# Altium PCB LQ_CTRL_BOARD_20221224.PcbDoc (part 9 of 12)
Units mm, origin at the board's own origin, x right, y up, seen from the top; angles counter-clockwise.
Board outline 260 x 142 mm, 6 copper layers (Top Layer, Mid-Layer 1, Mid-Layer 2, Mid-Layer 3, Mid-Layer 4, Bottom Layer); 1105 components, 1039 nets, 3898 pads, 1277 vias.
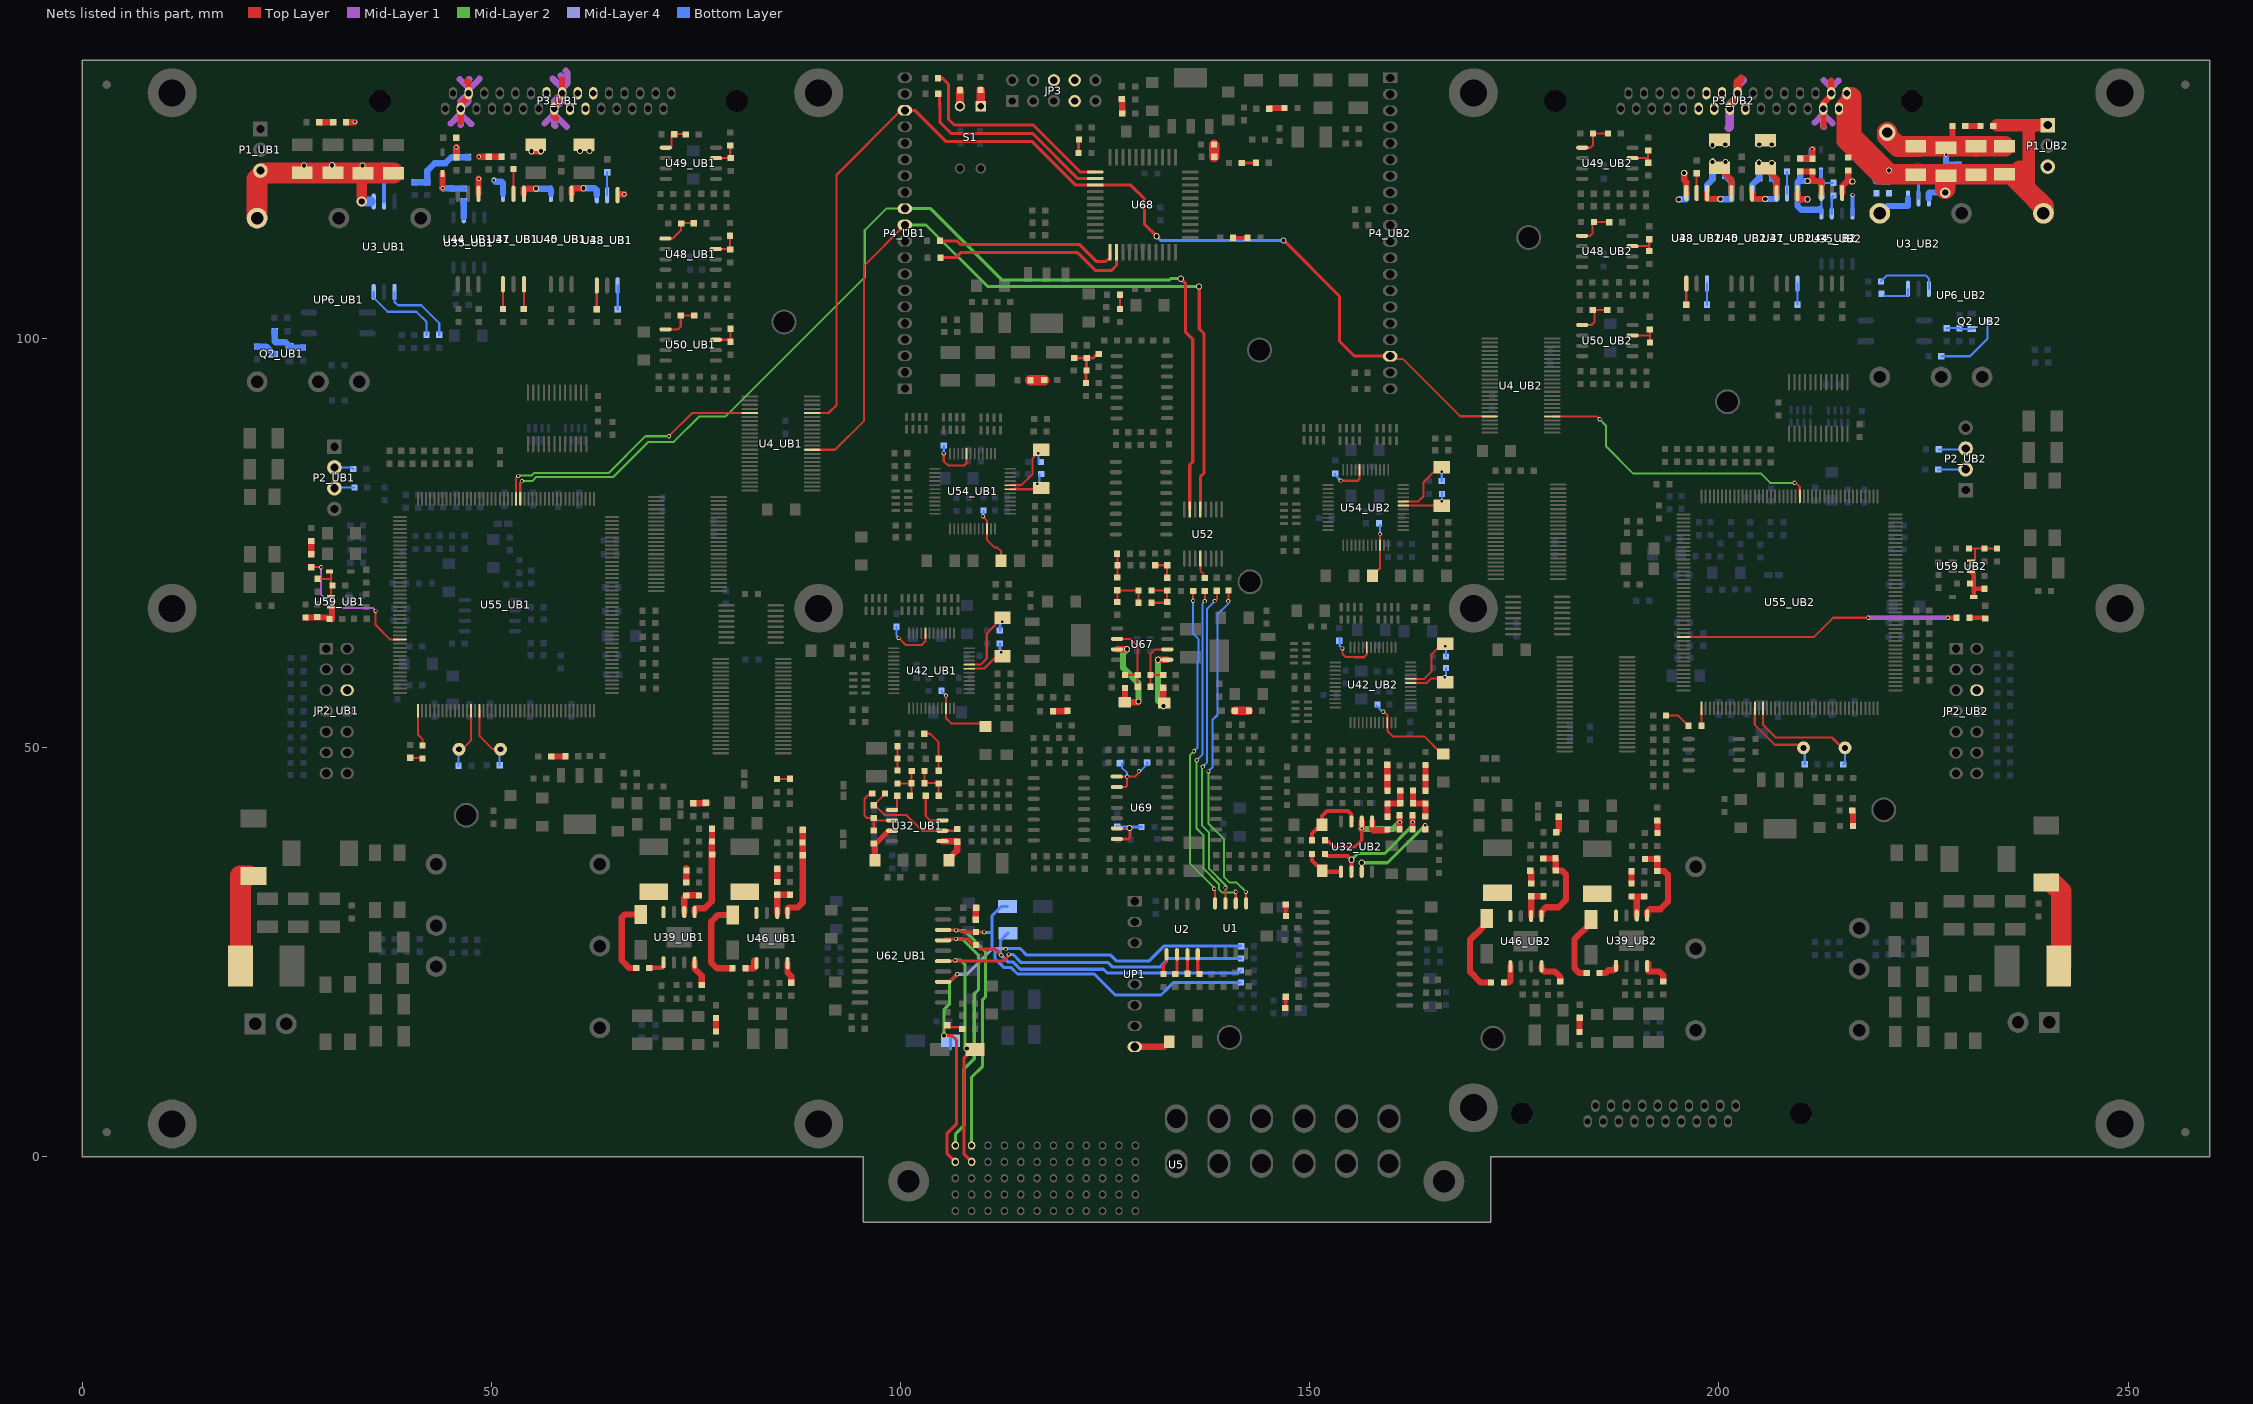
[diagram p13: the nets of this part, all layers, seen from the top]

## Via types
v1: diameter 0.508, hole 0.305, Top Layer to Bottom Layer, 845 vias
v2: diameter 0.762, hole 0.508, Top Layer to Bottom Layer, 317 vias
v3: diameter 1.27, hole 0.762, Top Layer to Bottom Layer, 77 vias
v4: diameter 2.032, hole 1.524, Top Layer to Bottom Layer, 15 vias
v5: diameter 2.032, hole 1.27, Top Layer to Bottom Layer, 11 vias
v6: diameter 1.27, hole 0.711, Top Layer to Bottom Layer, 8 vias
v7: diameter 2.54, hole 1.778, Top Layer to Bottom Layer, 3 vias
v8: diameter 1.524, hole 1.016, Top Layer to Bottom Layer, 1 vias

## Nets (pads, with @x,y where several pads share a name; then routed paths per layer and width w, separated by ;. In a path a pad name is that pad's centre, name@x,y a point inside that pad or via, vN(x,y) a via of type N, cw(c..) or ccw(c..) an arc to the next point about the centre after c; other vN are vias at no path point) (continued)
ISO_+15V_UB2: C12_UB2.1 C13_UB2.2 C14_UB2.2 C15_UB2.2 C256_UB2.1 C257_UB2.1 C278_UB2.1 C279_UB2.1 C280_UB2.2 C281_UB2.2 C282_UB2.2 C283_UB2.1 C305_UB2.2 C306_UB2.2 C307_UB2.2 C308_UB2.2 LED10_UB2.1 P1_UB2.1 P3_UB2.1 P3_UB2.16 R192_UB2.1 U3_UB2.6 U35_UB2.1 U35_UB2.4 U37_UB2.6 U38_UB2.6 U40_UB2.6 U41_UB2.6 U43_UB2.6 U44_UB2.6 U45_UB2.6 UP6_UB2.3 | length 114.9
  Top Layer w0.762: v2(195.758,120.193) 195.758,119.355 196.017,119.095 U38_UB2.6@196.017,117.754 ; C257_UB2.1@200.076,120.828 200.101,120.828 201.529,119.4 U45_UB2.6@201.529,117.729 ; C256_UB2.1@205.689,120.802 207.06,119.432 U41_UB2.6@207.06,117.729 ; C307_UB2.2@209.931,120.396 209.956,120.371 C308_UB2.2@211.43,120.371 211.43,119.253 211.455,119.228 ; v2(210.845,119.228) 211.455,119.228 ; U44_UB2.6@212.527,117.754 212.527,119.121 212.42,119.228 211.455,119.228 ; v3(227.658,117.805) v3@227.66,117.803 ; 237.298,125.959 237.851,125.405
  Top Layer w1.016: 216.281,130.124 214.859,128.702 214.859,123.952 219.558,119.253 ; 219.583,119.278 221.691,119.278
  Top Layer w1.524: 233.959,126.009 234.01,126.06 238.506,126.06 ; C279_UB2.1@235.735,120.04 236.675,120.98 237.851,120.98 ; 237.298,125.959 238.404,125.959 ; 237.679,118.096 237.851,118.268 237.851,120.98 ; P1_UB2.1@240.182,126.06 238.506,126.06 ; 237.851,120.98 237.851,125.405 238.404,125.959 ; 238.404,125.959 238.506,126.06
  Top Layer w2.54: 216.179,123.977 216.179,129.464 ; 216.281,124.638 220.878,120.04 C279_UB2.1@234.905,120.04 235.735,120.04 237.679,118.096 239.658,116.118 UP6_UB2.3@239.658,115.275 ; v3@227.66,118.313 C283_UB2.1@227.66,119.863
  Bottom Layer w0.254: U35_UB2.1@212.522,115.189 U35_UB2.1@212.522,115.24 212.522,117.399 R192_UB2.1@212.547,117.424
  Bottom Layer w0.508: U35_UB2.4@216.332,115.189 v1@216.332,117.504
  Bottom Layer w0.762: U43_UB2.6@198.557,117.754 198.557,118.75 199.238,119.431 v2(199.238,121.564) ; U40_UB2.6@204.069,117.729 204.069,118.75 204.902,119.583 v2(204.902,121.463) ; C282_UB2.2@209.931,120.396 209.931,119.378 209.781,119.228 ; v2(210.845,119.228) 209.781,119.228 ; U35_UB2.1@212.369,115.875 212.217,115.722 210.083,115.722 209.6,116.206 U37_UB2.6@209.6,117.729 209.6,119.046 209.781,119.228 ; U3_UB2.6@225.654,117.094 225.654,117.704 225.755,117.805 v3(227.658,117.805) 227.762,117.909 C14_UB2.2@227.762,119.659 C13_UB2.2@229.286,119.659
  Bottom Layer w1.016: C15_UB2.2@219.253,119.304 C306_UB2.2@220.777,119.304 v2(220.777,120.523)
  other v1: 216.337,117.526
  other v2: 206.451,121.437 200.812,121.539
ISO_GND_UB1: C12_UB1.2 C13_UB1.1 C14_UB1.1 C15_UB1.1 C256_UB1.2 C257_UB1.2 C278_UB1.2 C279_UB1.2 C280_UB1.1 C281_UB1.1 C282_UB1.1 C283_UB1.2 C305_UB1.1 C306_UB1.1 C307_UB1.1 C308_UB1.1 P1_UB1.3 P3_UB1.2 P3_UB1.8 P3_UB1.17 P3_UB1.23 R275_UB1.1 U3_UB1.4 U37_UB1.4 U38_UB1.4 U40_UB1.4 U41_UB1.4 U43_UB1.4 U44_UB1.4 U45_UB1.4 UP6_UB1.5 | length 100.5
  Top Layer w0.762: R275_UB1.1@32.258,126.416 33.299,126.416 v1(33.325,126.441) ; C281_UB1.1@45.745,122.123 v1(45.745,123.342) ; 46.177,126.416 46.279,126.517 P3_UB1.2@46.279,128.047 46.279,128.6 47.231,129.552 P3_UB1.17@47.231,129.952 47.231,131.204 47.015,131.42 ; U44_UB1.4@48.444,117.653 48.444,119.507 v1(48.463,119.507) ; v1(48.489,122.199) C14_UB1.1@49.682,122.199 C282_UB1.1@51.257,122.199 ; U37_UB1.4@53.98,117.653 53.98,118.268 v2@55.479,118.268 ; C256_UB1.2@55.428,123.647 55.428,123.373 v2(54.915,122.86) 56.044,122.86 v2(56.058,122.873) ; 57.887,126.873 57.709,127.051 P3_UB1.8@57.709,128.047 57.709,128.422 58.661,129.374 P3_UB1.23@58.661,129.952 58.661,131.61 58.674,131.623 ; U40_UB1.4@59.822,117.653 59.822,118.344 v2(61.259,118.344) v2@61.265,118.339 ; U43_UB1.4@65.634,117.602 v1(66.243,117.602)
  Top Layer w1.27: v3(34.163,116.713) 34.163,120.046 C279_UB1.2@34.31,120.193
  Top Layer w2.54: UP6_UB1.5@21.385,114.691 21.385,119.429 22.149,120.193 C279_UB1.2@34.31,120.193 C278_UB1.2@38.044,120.193
  Mid-Layer 1 w0.762: 45.034,126.238 P3_UB1.2@46.279,127.483 ; 46.152,131.648 P3_UB1.17@47.231,130.569 ; 46.228,126.06 46.279,126.111 P3_UB1.2@46.279,127.406 ; 47.295,131.699 47.231,131.635 P3_UB1.17@47.231,130.569 ; 47.549,126.187 47.523,126.213 47.473,126.213 P3_UB1.2@46.279,127.406 ; 48.565,131.724 P3_UB1.17@47.231,130.39 ; 56.515,126.263 P3_UB1.8@57.709,127.457 ; 57.48,131.75 P3_UB1.23@58.661,130.569 ; 57.785,125.933 57.81,125.959 57.709,126.06 P3_UB1.8@57.709,127.377 ; 58.496,132.105 58.661,131.941 P3_UB1.23@58.661,130.569 ; 59.106,132.69 59.309,132.486 59.309,131.14 P3_UB1.23@58.661,130.492 ; 59.233,125.853 P3_UB1.8@57.709,127.377 ; P3_UB1.2@46.279,127.406 P3_UB1.2@46.279,127.483 ; P3_UB1.2@46.279,127.483 P3_UB1.2@46.279,128.047 ; P3_UB1.2@46.279,128.047 47.231,128.999 P3_UB1.17@47.231,129.952 ; P3_UB1.2@46.279,128.047 46.279,129 P3_UB1.17@47.231,129.952 ; P3_UB1.17@47.231,129.952 P3_UB1.17@47.231,130.39 ; P3_UB1.17@47.231,130.39 P3_UB1.17@47.231,130.569 ; P3_UB1.8@57.709,127.377 P3_UB1.8@57.709,127.457 ; P3_UB1.8@57.709,127.457 P3_UB1.8@57.709,128.047 ; P3_UB1.8@57.709,128.047 58.661,128.999 P3_UB1.23@58.661,129.952 ; P3_UB1.8@57.709,128.047 57.709,129 P3_UB1.23@58.661,129.952 ; P3_UB1.23@58.661,129.952 P3_UB1.23@58.661,130.492 ; P3_UB1.23@58.661,130.492 P3_UB1.23@58.661,130.569
  Bottom Layer w0.762: C280_UB1.1@40.64,119.075 42.164,119.075 C13_UB1.1@42.189,119.05 ; C13_UB1.1@42.189,119.075 42.189,120.498 43.078,121.387 44.399,121.387 45.136,122.123 C305_UB1.1@45.745,122.123 ; v1(45.745,123.342) C305_UB1.1@45.745,122.123 ; C306_UB1.1@47.168,122.123 C305_UB1.1@45.745,122.123 ; v1(50.317,119.329) 50.521,119.126 51.257,119.126 51.44,118.943 U41_UB1.4@51.44,117.653 ; v2(55.474,118.288) 57.15,118.288 57.282,118.155 U45_UB1.4@57.282,117.653 ; v2(61.259,118.344) 62.631,118.344 62.89,118.085 U38_UB1.4@62.89,117.5
  Bottom Layer w1.27: v3(34.163,116.713) 35.204,116.713
  other v2: 27.102,121.133 34.265,121.133 30.556,121.158 62.001,122.885 60.833,122.911
ISO_GND_UB2: C12_UB2.2 C13_UB2.1 C14_UB2.1 C15_UB2.1 C256_UB2.2 C257_UB2.2 C278_UB2.2 C279_UB2.2 C280_UB2.1 C281_UB2.1 C282_UB2.1 C283_UB2.2 C305_UB2.1 C306_UB2.1 C307_UB2.1 C308_UB2.1 P1_UB2.3 P3_UB2.2 P3_UB2.8 P3_UB2.17 P3_UB2.23 R275_UB2.1 U3_UB2.4 U37_UB2.4 U38_UB2.4 U40_UB2.4 U41_UB2.4 U43_UB2.4 U44_UB2.4 U45_UB2.4 UP6_UB2.5 | length 79.1
  Top Layer w0.762: U38_UB2.4@198.557,117.754 198.557,117.063 198.603,117.018 v2(200.177,117.018) ; U45_UB2.4@204.069,117.729 204.069,117.216 204.267,117.018 v2(205.664,117.018) ; U41_UB2.4@209.6,117.729 209.6,117.07 209.677,116.992 v2(210.82,116.992) ; C307_UB2.1@209.931,121.971 211.404,121.971 C308_UB2.1@211.43,121.945 211.43,123.038 211.48,123.088 211.455,123.114 v1(211.43,123.114) ; P3_UB2.17@212.766,128.047 P3_UB2.17@212.766,128.695 ; 212.776,125.984 P3_UB2.17@212.776,128.055 ; P3_UB2.17@212.801,128.753 P3_UB2.2@213.753,129.705 ; 213.69,131.47 213.718,131.443 P3_UB2.2@213.718,129.952 ; U44_UB2.4@215.067,117.754 215.067,118.573 215.671,119.177 ; C305_UB2.1@215.798,120.523 215.798,119.304 215.671,119.177 ; v2(216.306,119.177) 215.671,119.177 ; C283_UB2.2@227.736,123.292 227.914,123.469 228.54,124.095 R275_UB2.1@228.54,125.959
  Top Layer w1.016: P3_UB2.23@201.336,128.047 201.336,128.514 202.288,129.466 P3_UB2.8@202.288,129.952 202.288,131.295 202.692,131.699
  Top Layer w2.54: v5(220.574,125.146) 220.574,124.739 221.869,123.444 C12_UB2.2@224.053,123.444 ; C12_UB2.2@224.516,123.444 C12_UB2.2@224.053,123.444 ; C278_UB2.2@231.419,123.444 C278_UB2.2@231.419,123.469 ; C279_UB2.2@234.905,123.469 C278_UB2.2@231.419,123.469 ; C12_UB2.2@224.053,123.444 224.079,123.469 227.914,123.469 C278_UB2.2@231.419,123.469
  Mid-Layer 1 w0.762: 211.709,126.365 P3_UB2.17@212.766,127.422 ; P3_UB2.17@212.766,128.047 P3_UB2.17@212.766,127.422 ; 212.827,125.832 212.766,125.892 P3_UB2.17@212.766,127.391 ; 212.827,131.521 212.827,131.54 213.718,130.648 P3_UB2.2@213.718,130.584 ; P3_UB2.2@213.718,129.952 P3_UB2.2@213.718,130.584 ; 213.893,126.263 P3_UB2.17@212.766,127.391 ; 214.605,131.47 P3_UB2.2@213.718,130.584 ; P3_UB2.17@212.766,127.391 P3_UB2.17@212.766,127.422
  Mid-Layer 1 w1.016: 201.219,125.73 201.336,125.847 P3_UB2.23@201.336,128.047 201.336,128.514 202.288,129.466 P3_UB2.8@202.288,129.952 202.288,130.882 202.946,131.54
  Bottom Layer w0.762: v2@195.275,116.992 196.017,116.992 U43_UB2.4@196.017,117.754 ; v2(200.177,117.018) 200.197,116.998 201.529,116.998 U40_UB2.4@201.529,117.729 201.529,119.121 C280_UB2.1@200.787,119.863 ; v2(205.664,117.018) 206.985,117.018 207.086,117.119 207.06,117.146 U37_UB2.4@207.06,117.729 207.06,119 C281_UB2.1@206.502,119.558 ; C282_UB2.1@209.931,121.971 211.328,121.971 211.353,121.945 211.353,123.038 v1(211.43,123.114) ; UP6_UB2.5@219.658,115.275 220.562,116.18 223.114,116.18 U3_UB2.4@223.114,117.094 ; v1(227.762,122.403) C14_UB2.1@227.762,121.234 C13_UB2.1@229.286,121.234
  Bottom Layer w1.016: P3_UB2.23@201.336,128.047 201.336,128.565 202.288,129.517 P3_UB2.8@202.288,129.952
  other v2: 195.097,116.967 199.238,123.596 200.787,123.673 204.927,123.673 206.451,123.698
LED1_UB1: R347_UB1.1 U55_UB1.89 | length 4.5
  Top Layer w0.254: U55_UB1.89@41.04,54.491 41.04,53.232 41.04,51.579 41.605,51.014 R347_UB1.1@41.605,50.241
LED1_UB2: R347_UB2.1 U55_UB2.89 | length 2.1
  Top Layer w0.254: R347_UB2.1@197.866,52.654 197.885,52.673 U55_UB2.89@197.885,54.796
LED2_UB1: R41_UB1.1 U55_UB1.75 | length 17.6
  Top Layer w0.254: R41_UB1.1@27.991,72.034 29.197,72.034 29.235,71.996 29.235,72.009 v1(29.21,72.034) ; v1(35.87,66.691) 35.87,64.968 37.647,63.191 U55_UB1.75@38.84,63.191
  Mid-Layer 1 w0.254: v1(29.21,72.034) 29.21,68.682 30.861,67.031 34.505,67.031 34.531,67.056 35.505,67.056 v1(35.87,66.691)
LED2_UB2: R41_UB2.1 U55_UB2.75 | length 34.3
  Top Layer w0.254: U55_UB2.75@195.685,63.496 211.603,63.496 213.97,65.862 v1(218.262,65.862)
  Top Layer w0.508: v1(227.99,65.862) R41_UB2.1@229.033,65.862
  Mid-Layer 1 w0.508: v1(218.262,65.862) v1(227.99,65.862)
M_EXT_IO_IN1: R391.2 U68.2 | length 25.7
  Top Layer w0.381: 104.775,128.397 R391.2@104.775,129.896 ; 104.826,128.778 104.826,126.39 106.172,125.044 116.129,125.044 121.653,119.52 U68.2@123.8,119.52
M_EXT_IO_IN2: R392.2 U68.1 | length 26.3
  Top Layer w0.381: R392.2@104.775,131.775 105.131,131.775 105.867,131.039 105.867,126.771 106.578,126.06 116.214,126.06 121.955,120.32 U68.1@123.8,120.32
M_EXT_IO_OUT1: R393.2 U68.13 | length 24.6
  Top Layer w0.381: R393.2@104.877,109.855 106.756,109.855 107.366,110.465 121.539,110.465 ; 121.59,110.414 121.539,110.465 ; U68.13@126.4,110.52 126.4,108.899 125.806,108.306 123.8,108.306 121.641,110.465 121.539,110.465
M_EXT_IO_OUT2: R394.2 U68.12 | length 22.7
  Top Layer w0.381: R394.2@104.826,111.912 106.883,111.912 107.315,111.481 121.844,111.481 123.927,109.398 125.12,109.398 125.6,109.877 U68.12@125.6,110.52
M_RS422_A: DR6.2 R366_UB1.2 R421.1 U5.E2 U62_UB1.18 | length 75.4
  Top Layer w0.381: U62_UB1.18@105.212,27.711 107.213,27.711 107.467,27.457 R366_UB1.2@109.22,27.457 v1@110.211,27.457
  Mid-Layer 2 w0.381: v1(106.807,27.661) 107.772,27.661 110.388,25.044 110.388,19.533 110.033,19.177 110.033,11.074 108.7,9.742 U5.E2@108.7,1.373
  Bottom Layer w0.254: R421.1@141.326,21.285 R421.1@141.605,21.285
  Bottom Layer w0.381: v1(110.236,27.407) 111.1,27.407 111.176,27.33 ; DR6.2@113.073,30.582 112.311,30.582 111.176,29.446 111.176,27.33 ; 132.651,20.587 132.639,20.574 ; R421.1@141.326,21.285 133.35,21.285 132.639,20.574 ; 111.176,27.33 111.176,25.451 111.557,25.07 111.557,24.181 112.598,23.139 113.487,23.139 114.3,22.327 123.673,22.327 126.238,19.761 131.826,19.761 132.639,20.574
M_RS422_B: DR8.2 R366_UB1.1 R422.1 U5.E1 U62_UB1.17 | length 70
  Top Layer w0.381: U62_UB1.17@105.212,26.441 105.39,26.619 v1(106.782,26.619) 108.153,26.619 108.89,25.883 R366_UB1.1@109.22,25.883 109.728,25.375 111.557,25.375 v1(112.319,24.613)
  Mid-Layer 2 w0.381: U5.E1@106.7,1.373 106.7,2.738 107.798,3.835 107.798,10.744 ; v1(106.782,26.619) 107.518,26.619 109.525,24.613 109.525,20.422 109.017,19.914 109.017,11.963 107.798,10.744 ; 108.267,11.214 107.798,10.744
  Bottom Layer w0.254: R422.1@141.275,22.454 R422.1@141.58,22.758
  Bottom Layer w0.381: DR8.2@113.124,27.305 112.23,26.411 112.23,24.701 v1(112.319,24.613) 113.157,23.774 113.784,23.774 114.647,22.911 124.816,22.911 125.273,22.454 R422.1@141.275,22.454
M_RS422_Y: DR5.2 R424.1 U5.D1 U62_UB1.13 | length 66.7
  Top Layer w0.381: U62_UB1.13@105.212,21.361 105.969,21.361 v1@106.921,22.314 ; v2(105.334,14.808) 106.274,14.808 106.858,14.224 106.858,4.013 105.664,2.819 105.664,0.409 U5.D1@106.7,-0.627
  Mid-Layer 2 w0.381: v2(105.334,14.808) 105.334,18.009 106.007,18.682 106.007,21.374 v1(106.934,22.301) ; U5.D1@106.667,-0.66 U5.D1@106.7,-0.627
  Mid-Layer 4 w0.381: v1(106.934,22.301) 108.128,22.301 111.277,25.451 v1@112.751,25.451
  Bottom Layer w0.381: 106.103,13.183 106.121,13.201 DR5.2@106.121,14.707 ; v1@112.878,25.451 114.63,25.451 115.443,24.638 125.705,24.638 126.441,23.901 130.353,23.901 132.182,25.73 R424.1@141.63,25.73
  other v1: 112.878,25.375
M_RS422_Z: DR7.2 R423.1 U5.D2 U62_UB1.15 | length 64.4
  Top Layer w0.381: U62_UB1.15@105.212,23.901 112.573,23.901 113.208,24.536 v1@113.208,24.714 ; U5.D2@108.7,-0.627 107.772,0.301 107.772,12.09 108.788,13.106 DR7.2@109.1,13.106
  Mid-Layer 2 w0.381: v1(106.705,24.003) 107.366,24.003 107.899,23.47 107.899,21.339 107.861,21.301 v2@107.861,13.233
  Bottom Layer w0.381: v1(113.233,24.714) 113.76,24.714 114.75,23.724 125.4,23.724 125.959,23.165 131.674,23.165 132.74,24.232 R423.1@141.605,24.232
  other v2: 108.102,13.233
M_SYN_CLK: P4_UB1.11 U4_UB1.11 U52.5 | length 100.5
  Top Layer w0.254: U4_UB1.11@89.205,86.382 91.995,86.382 95.555,89.941 95.555,108.875 P4_UB1.11@100.533,113.853
  Top Layer w0.381: v2@136.5,106.324 136.5,101.168 137.084,100.584 137.084,83.515 136.643,83.074 U52.5@136.643,79.087
  Mid-Layer 2 w0.381: P4_UB1.11@100.533,113.853 100.543,113.843 103.124,113.843 110.642,106.324 v2(136.474,106.324)
M_SYN_CLKIN: P4_UB1.12 U52.7 U55_UB1.19 | length 132.8
  Top Layer w0.254: U55_UB1.19@53.54,80.391 53.54,82.395 v1@53.721,82.575
  Top Layer w0.381: v2(134.239,107.29) 134.849,106.68 134.849,100.762 135.712,99.898 135.712,84.912 135.343,84.543 U52.7@135.343,79.087
  Mid-Layer 2 w0.254: v1(53.746,82.55) 54.991,82.55 55.499,83.058 64.922,83.058 69.215,87.351 72.314,87.351 ; 72.111,87.351 72.314,87.351 ; P4_UB1.12@100.533,115.853 98.276,115.853 95.631,113.208 95.631,107.467 78.588,90.424 75.387,90.424 72.314,87.351
  Mid-Layer 2 w0.381: P4_UB1.12@100.533,115.853 103.679,115.853 112.42,107.112 132.817,107.112 132.994,107.29 v2(134.239,107.29)
M_SYNC_CLK: R8.1 U52.12 | length 2.6
  Top Layer w0.254: U52.12@136.643,73.087 136.643,71.586 137.185,71.044 R8.1@137.185,70.714
MS_SLT: P4_UB1.18 P4_UB2.18 U4_UB1.20 U4_UB2.20 U68.3 | length 135.9
  Top Layer w0.254: U4_UB1.20@89.205,90.882 91.212,90.882 92.177,91.846 92.177,119.964 100.065,127.853 P4_UB1.18@100.533,127.853 ; P4_UB2.18@159.573,97.841 159.929,97.485 161.366,97.485 168.377,90.475 U4_UB2.20@172.771,90.475
  Top Layer w0.381: P4_UB1.18@100.533,127.853 101.763,127.853 105.588,124.028 116.103,124.028 121.412,118.72 U68.3@123.8,118.72 128.143,118.72 129.819,117.043 129.819,113.944 v2(131.293,112.471) ; v2(146.812,111.963) 153.645,105.131 153.645,99.644 155.448,97.841 P4_UB2.18@159.573,97.841
  Bottom Layer w0.381: v2(131.293,112.471) 131.826,111.938 143.383,111.938 143.408,111.963 v2(146.812,111.963)
MS_SLT_IN_UB1: U4_UB1.29 U55_UB1.20 | length 34.4
  Top Layer w0.254: U55_UB1.20@53.04,80.391 53.04,82.961 v1@53.34,83.261 ; v1(71.704,88.036) 74.549,90.882 U4_UB1.29@81.585,90.882
  Mid-Layer 2 w0.254: v1@53.34,83.261 54.966,83.261 55.245,83.541 64.338,83.541 68.834,88.036 v1(71.704,88.036)
  other v1: 53.289,83.185
MS_SLT_IN_UB2: U4_UB2.29 U55_UB2.20 | length 36.2
  Top Layer w0.254: U4_UB2.29@179.629,90.474 185.065,90.474 v1(185.42,90.119) ; v1@209.454,82.291 209.454,82.279 209.885,81.848 U55_UB2.20@209.885,80.696
  Mid-Layer 2 w0.254: v1(185.42,90.119) 186.207,89.332 186.207,86.792 189.535,83.464 205.156,83.464 206.273,82.347 v1(209.245,82.347)
NetC5_2: C5.2 UP1.8 | length 4.5
  Top Layer w0.762: UP1.8@128.626,13.437 132.232,13.437 C5.2@132.842,14.046
NetC224_UB1_2: C224_UB1.2 R207_UB1.2 U32_UB1.1 | length 4.5
  Top Layer w0.508: C224_UB1.2@105.933,36.246 C224_UB1.2@105.933,36.409 ; R207_UB1.2@106.872,38.557 R207_UB1.2@106.949,38.481
  Top Layer w0.762: U32_UB1.1@105.12,38.557 R207_UB1.2@106.872,38.557 ; C224_UB1.2@105.933,36.409 106.949,37.425 R207_UB1.2@106.949,38.481
NetC224_UB2_2: C224_UB2.2 R207_UB2.2 U32_UB2.1 | length 4.9
  Top Layer w0.508: R207_UB2.2@150.292,36.982 150.292,36.195 C224_UB2.2@151.536,34.95 151.663,34.823 U32_UB2.1@153.822,34.823
NetC225_UB1_1: C225_UB1.1 R195_UB1.1 R203_UB1.2 | length 5.7
  Top Layer w0.254: C225_UB1.1@102.895,51.689 103.099,51.689 103.619,51.689 104.663,50.645 104.663,50.125 R195_UB1.1@104.663,47.168
NetC225_UB2_1: C225_UB2.1 R195_UB2.1 R203_UB2.2 | length 3.1
  Top Layer w0.762: R195_UB2.1@164.16,44.729 R203_UB2.2@164.16,46.31 C225_UB2.1@164.16,47.879
NetC236_UB1_1: C236_UB1.1 R207_UB1.1 R209_UB1.2 U32_UB1.2 | length 13.6
  Top Layer w0.254: C236_UB1.1@98.12,44.399 98.12,44.334 R209_UB1.2@96.738,42.951 96.876,42.951 98.069,41.758 100.711,41.758 102.641,39.827 U32_UB1.2@105.12,39.827 106.72,39.827 R207_UB1.1@106.949,40.056
NetC236_UB1_2: C236_UB1.2 R209_UB1.1 R214_UB1.1 U32_UB1.6 | length 8.4
  Top Layer w0.254: C236_UB1.2@96.545,44.399 96.266,44.399 95.58,43.713 95.58,41.707 95.91,41.377 R209_UB1.1@96.738,41.377 ; R214_UB1.1@96.738,39.853 R209_UB1.1@96.738,41.377 ; U32_UB1.6@98.973,41.097 97.017,41.097 R209_UB1.1@96.738,41.377
NetC236_UB2_1: C236_UB2.1 R207_UB2.1 R209_UB2.2 U32_UB2.2 | length 16.1
  Top Layer w0.381: R207_UB2.1@151.867,36.982 R207_UB2.1@152.121,36.728 ; v2@155.092,36.271 v2(155.118,36.297)
  Top Layer w0.508: R207_UB2.1@152.121,36.728 154.635,36.728 155.092,36.271 U32_UB2.2@155.092,34.823
  Top Layer w0.762: R209_UB2.2@162.56,40.005 C236_UB2.1@162.56,41.504
  Mid-Layer 2 w0.381: v2(155.118,36.297) 155.88,37.059 159.156,37.059 162.585,40.488 v1(162.585,40.894)
NetC236_UB2_2: C236_UB2.2 R209_UB2.1 R214_UB2.1 U32_UB2.6 | length 13.9
  Top Layer w0.381: R214_UB2.1@151.867,38.659 152.146,38.659 152.959,37.846 155.524,37.846 156.362,38.684 v1@156.362,40.056
  Top Layer w0.762: v1@156.362,40.056 v1(156.362,40.107) U32_UB2.6@156.362,40.97 ; R209_UB2.1@160.985,40.005 C236_UB2.2@160.985,41.504
  Mid-Layer 2 w0.762: v1@156.362,40.056 160.198,40.056 v1@160.985,40.843
  other v1: 161.011,40.894
NetC241_UB1_1: C241_UB1.1 R212_UB1.1 R221_UB1.2 R222_UB1.1 | length 4.8
  Top Layer w0.254: R221_UB1.2@99.644,45.618 101.335,45.618 C241_UB1.1@101.361,45.644 ; R222_UB1.1@101.168,44.12 101.371,44.323 R212_UB1.1@101.371,47.117
NetC241_UB1_2: C241_UB1.2 R195_UB1.2 R196_UB1.1 R212_UB1.2 | length 4.7
  Top Layer w0.254: R212_UB1.2@102.946,47.117 102.946,45.655 C241_UB1.2@102.935,45.644 104.612,45.644 R195_UB1.2@104.663,45.593 R196_UB1.1@104.663,44.12
NetC241_UB2_1: C241_UB2.1 R212_UB2.1 R221_UB2.2 R222_UB2.1 | length 4.7
  Top Layer w0.762: R222_UB2.1@159.512,41.554 R221_UB2.2@159.512,43.155 161.03,43.155 R212_UB2.1@161.061,43.186 161.06,43.187 C241_UB2.1@161.06,44.761
NetC241_UB2_2: C241_UB2.2 R195_UB2.2 R196_UB2.1 R212_UB2.2 | length 4.7
  Top Layer w0.762: C241_UB2.2@162.635,44.761 162.635,43.187 R212_UB2.2@162.636,43.186 162.667,43.155 R195_UB2.2@164.16,43.155 164.16,41.636 R196_UB2.1@164.109,41.586
NetC248_UB1_1: C248_UB1.1 R219_UB1.1 R221_UB1.1 | length 3
  Top Layer w0.254: R221_UB1.1@99.644,47.193 R219_UB1.1@99.644,48.653 C248_UB1.1@99.644,50.165
NetC248_UB2_1: C248_UB2.1 R219_UB2.1 R221_UB2.1 | length 3.2
  Top Layer w0.762: C248_UB2.1@159.487,47.904 159.487,44.755 R221_UB2.1@159.512,44.729
NetC250_UB1_2: C250_UB1.2 R214_UB1.2 U32_UB1.7 | length 4.7
  Top Layer w0.254: U32_UB1.7@98.552,39.827 U32_UB1.7@98.973,39.827
  Top Layer w0.635: R214_UB1.2@96.876,38.151 U32_UB1.7@98.552,39.827
  Top Layer w0.762: C250_UB1.2@96.876,36.22 R214_UB1.2@96.876,38.151
NetC250_UB2_2: C250_UB2.2 R214_UB2.2 U32_UB2.7 | length 8.4
  Top Layer w0.508: R214_UB2.2@150.292,38.659 150.292,39.472 151.409,40.589 C250_UB2.2@151.511,40.589 151.511,41.631 152.121,42.24 154.661,42.24 155.092,41.808 U32_UB2.7@155.092,40.97
NetC252_UB1_1: C252_UB1.1 D20_UB1.2 L3_UB1.2 U39_UB1.8 | length 9.9
  Top Layer w0.762: C252_UB1.1@67.716,23.063 66.878,23.063 65.938,24.003 65.938,29.235 66.301,29.598 D20_UB1.2@68.25,29.598
NetC252_UB1_2: C252_UB1.2 U39_UB1.1 | length 2.4
  Top Layer w0.508: C252_UB1.2@69.19,23.089 70.841,23.089 71.044,23.292 U39_UB1.1@71.044,23.749
NetC252_UB2_1: C252_UB2.1 D20_UB2.2 L3_UB2.2 U39_UB2.8 | length 8.5
  Top Layer w0.762: C252_UB2.1@183.845,22.454 182.956,22.454 182.347,23.063 182.347,26.568 184.379,28.6 D20_UB2.2@184.379,28.989
NetC252_UB2_2: C252_UB2.2 U39_UB2.1 | length 2.5
  Top Layer w0.762: C252_UB2.2@185.42,22.454 186.157,22.454 186.487,22.784 187.122,22.784 187.427,23.089 U39_UB2.1@187.427,23.317
NetC258_UB1_2: C258_UB1.2 R238_UB1.1 R242_UB1.2 U39_UB1.5 | length 11.6
  Top Layer w0.762: U39_UB1.5@74.854,29.896 74.854,30.277 74.93,30.353 76.098,30.353 76.937,31.191 R238_UB1.1@76.937,38.43 ; R238_UB1.1@76.962,38.532 C258_UB1.2@76.962,40.081
NetC258_UB2_2: C258_UB2.2 R238_UB2.1 R242_UB2.2 U39_UB2.5 | length 11.3
  Top Layer w0.762: C258_UB2.2@190.957,36.373 192.43,36.373 R238_UB2.1@192.456,36.398 192.456,34.925 R242_UB2.2@192.481,34.9 193.345,34.9 193.777,34.468 193.777,31.166 192.862,30.251 191.541,30.251 191.237,29.947 U39_UB2.5@191.237,29.464
NetC267_UB1_1: C267_UB1.1 C268_UB1.1 U42_UB1.46 | length 8.8
  Top Layer w0.254: v1(105.562,56.337) 105.549,56.323 U42_UB1.46@105.549,54.785 105.549,53.608 106.197,52.959 110.007,52.959 C267_UB1.1@110.388,52.578
  Bottom Layer w0.254: C268_UB1.1@105.004,56.947 105.004,56.896 v1(105.562,56.337)
NetC267_UB2_1: C267_UB2.1 C268_UB2.1 U42_UB2.46 | length 11.9
  Top Layer w0.254: v1(159.004,54.381) 159.029,54.407 159.029,54.432 159.484,53.978 U42_UB2.46@159.484,53.05 159.484,52.022 160.147,51.359 164.008,51.359 166.167,49.2 C267_UB2.1@166.345,49.2
  Bottom Layer w0.254: C268_UB2.1@158.14,55.143 158.902,54.381 v1(159.004,54.381)
NetC273_UB1_2: C273_UB1.2 U39_UB1.4 | length 3.1
  Top Layer w0.762: U39_UB1.4@74.854,23.749 74.854,22.987 75.717,22.123 C273_UB1.2@75.717,20.98
NetC273_UB2_2: C273_UB2.2 U39_UB2.4 | length 3.7
  Top Layer w0.762: U39_UB2.4@191.414,23.597 191.414,22.631 192.735,22.631 193.192,22.174 C273_UB2.2@193.192,21.412
NetC274_UB1_2: C274_UB1.2 C275_UB1.2 U39_UB1.6 | length 3.7
  Top Layer w0.762: U39_UB1.6@73.584,29.896 73.584,31.674 C275_UB1.2@73.838,31.928 73.863,31.953 C274_UB1.2@75.387,31.953
NetC274_UB2_2: C274_UB2.2 C275_UB2.2 U39_UB2.6 | length 3.8
  Top Layer w0.762: C275_UB2.2@189.362,31.801 C274_UB2.2@190.886,31.801 ; U39_UB2.6@189.967,29.464 189.967,31.725
NetC275_UB1_1: C275_UB1.1 R245_UB1.2 | length 1.8
  Top Layer w0.762: C275_UB1.1@73.838,33.503 73.838,35.276 R245_UB1.2@73.843,35.281
NetC275_UB2_1: C275_UB2.1 R245_UB2.2 | length 1.5
  Top Layer w0.762: C275_UB2.1@189.332,33.376 R245_UB2.2@189.332,34.874
NetC290_UB1_1: C290_UB1.1 D22_UB1.2 L4_UB1.2 U46_UB1.8 | length 10.8
  Top Layer w0.762: C290_UB1.1@79.477,23.038 77.572,23.038 76.886,23.724 76.886,28.727 77.706,29.548 D22_UB1.2@79.502,29.548
NetC290_UB1_2: C290_UB1.2 U46_UB1.1 | length 2
  Top Layer w0.762: C290_UB1.2@81.051,23.038 82.093,23.038 82.144,23.089 82.144,23.952
NetC290_UB2_1: C290_UB2.1 D22_UB2.2 L4_UB2.2 U46_UB2.8 | length 9.9
  Top Layer w0.762: D22_UB2.2@171.628,28.506 170.274,27.153 170.205,27.153 169.596,26.543 169.596,22.581 170.891,21.285 C290_UB2.1@172.161,21.285
NetC290_UB2_2: C290_UB2.2 U46_UB2.1 | length 2.6
  Top Layer w0.762: C290_UB2.2@173.736,21.285 174.295,21.285 174.523,21.514 U46_UB2.1@174.523,23.266
NetC293_UB1_2: C293_UB1.2 R268_UB1.1 R273_UB1.2 U46_UB1.5 | length 11.6
  Top Layer w0.762: U46_UB1.5@86.208,29.794 86.208,30.328 86.335,30.455 87.452,30.455 88.062,31.064 C293_UB1.2@88.062,39.954
NetC293_UB2_2: C293_UB2.2 R268_UB2.1 R273_UB2.2 U46_UB2.5 | length 11.7
  Top Layer w0.762: U46_UB2.5@178.333,29.413 178.333,29.947 178.867,30.48 180.416,30.48 181.305,31.369 181.305,34.493 180.823,34.976 R273_UB2.2@180.066,34.976 180.066,36.444 R268_UB2.1@180.035,36.474 180.01,36.449 C293_UB2.2@178.537,36.449
NetC296_UB1_2: C296_UB1.2 U46_UB1.4 | length 2.6
  Top Layer w0.762: U46_UB1.4@86.208,23.647 86.208,22.504 86.665,22.047 C296_UB1.2@86.665,21.26
NetC296_UB2_2: C296_UB2.2 U46_UB2.4 | length 3.5
  Top Layer w0.762: U46_UB2.4@178.333,23.266 178.333,22.987 178.689,22.631 179.959,22.631 180.619,21.971 C296_UB2.2@180.619,21.412
NetC297_UB1_2: C297_UB1.2 C298_UB1.2 U46_UB1.6 | length 3.7
  Top Layer w0.762: U46_UB1.6@84.938,29.794 C298_UB1.2@84.938,32.004 C297_UB1.2@86.411,32.004
NetC297_UB2_2: C297_UB2.2 C298_UB2.2 U46_UB2.6 | length 3.9
  Top Layer w0.762: U46_UB2.6@177.063,29.413 C298_UB2.2@177.063,31.826 C297_UB2.2@178.562,31.826
NetC298_UB1_1: C298_UB1.1 R276_UB1.2 | length 1.6
  Top Layer w0.762: C298_UB1.1@84.938,33.579 R276_UB1.2@84.938,35.179
NetC298_UB2_1: C298_UB2.1 R276_UB2.2 | length 1.6
  Top Layer w0.762: R276_UB2.2@176.962,34.95 177.063,34.849 C298_UB2.1@177.063,33.401
NetC302_UB1_2: C302_UB1.2 R270_UB1.2 U48_UB1.5 | length 4.7
  Top Layer w0.254: U48_UB1.5@71.278,112.192 72.161,112.192 73.177,113.208 73.177,114.071 C302_UB1.2@74.727,114.071
NetC302_UB2_2: C302_UB2.2 R270_UB2.2 U48_UB2.5 | length 4.8
  Top Layer w0.254: U48_UB2.5@183.286,112.527 184.257,112.527 184.582,112.852 184.582,114.198 C302_UB2.2@186.614,114.198
NetC303_UB1_2: C303_UB1.2 R271_UB1.2 U49_UB1.3 | length 3.1
  Top Layer w0.254: U49_UB1.3@77.462,122.022 79.212,122.022 C303_UB1.2@79.33,121.904 ; C303_UB1.2@79.197,122.25 R271_UB1.2@79.197,123.444
NetC303_UB2_2: C303_UB2.2 R271_UB2.2 U49_UB2.3 | length 3.4
  Top Layer w0.254: U49_UB2.3@189.459,122.022 191.364,122.022 ; C303_UB2.2@191.364,121.463 191.364,122.022 ; R271_UB2.2@191.364,122.961 191.364,122.022
NetC304_UB1_2: C304_UB1.2 R272_UB1.2 U50_UB1.5 | length 5
  Top Layer w0.254: U50_UB1.5@71.303,101.092 72.822,101.092 73.152,101.422 R272_UB1.2@73.152,102.794 C304_UB1.2@74.803,102.794
NetC304_UB2_2: C304_UB2.2 R272_UB2.2 U50_UB2.5 | length 4.7
  Top Layer w0.254: U50_UB2.5@183.312,101.625 184.441,101.625 184.785,101.969 184.785,103.454 C304_UB2.2@186.36,103.454
NetC310_UB1_2: C310_UB1.2 U42_UB1.8 Y3_UB1.2 | length 9.4
  Top Layer w0.254: U42_UB1.8@108.399,60.135 109.792,60.135 110.541,60.884 110.541,63.932 Y3_UB1.2@112.471,65.862
  Bottom Layer w0.381: C310_UB1.2@112.141,64.313 112.141,65.075 v1(112.42,65.354)
NetC310_UB2_2: C310_UB2.2 U42_UB2.8 Y3_UB2.2 | length 8.6
  Top Layer w0.254: U42_UB2.8@162.334,58.4 163.988,58.4 164.897,59.309 164.897,61.417 166.305,62.825 Y3_UB2.2@166.573,62.825
  Bottom Layer w0.254: v1(166.548,62.382) 166.548,62.357 166.649,62.255 C310_UB2.2@166.649,61.138
NetC322_UB1_2: C322_UB1.2 U42_UB1.7 Y3_UB1.1 | length 5.8
  Top Layer w0.254: U42_UB1.7@108.399,59.635 110.206,59.635 111.735,61.163 Y3_UB1.1@112.471,61.163
  Bottom Layer w0.381: C322_UB1.2@112.141,62.713 112.141,61.849 v1(112.319,61.671)
NetC322_UB2_2: C322_UB2.2 U42_UB2.7 Y3_UB2.1 | length 5.8
  Top Layer w0.254: U42_UB2.7@162.334,57.9 164.326,57.9 164.871,58.445 166.254,58.445 Y3_UB2.1@166.573,58.126
  Bottom Layer w0.254: v1(166.522,58.598) 166.649,58.725 C322_UB2.2@166.649,59.702
NetC326_UB1_2: C326_UB1.2 R288_UB1.2 U48_UB1.3 | length 3.5
  Top Layer w0.254: U48_UB1.3@77.425,110.922 79.121,110.922 C326_UB1.2@79.172,110.871 ; R288_UB1.2@79.172,112.522 C326_UB1.2@79.172,110.871 ; C326_UB1.2@79.197,110.846 C326_UB1.2@79.172,110.871
NetC326_UB2_2: C326_UB2.2 R288_UB2.2 U48_UB2.3 | length 3.5
  Top Layer w0.254: U48_UB2.3@189.433,111.257 191.445,111.257 191.491,111.303 ; C326_UB2.2@191.491,110.668 191.491,111.303 ; R288_UB2.2@191.491,112.116 191.491,111.303
NetC329_UB1_2: C329_UB1.2 R291_UB1.2 U49_UB1.5 | length 4.1
  Top Layer w0.254: U49_UB1.5@71.315,123.292 71.989,123.292 72.014,123.317 72.014,124.943 73.742,124.943 C329_UB1.2@73.767,124.917
NetC329_UB2_2: C329_UB2.2 R291_UB2.2 U49_UB2.5 | length 4.7
  Top Layer w0.254: U49_UB2.5@183.312,123.292 184.302,123.292 184.633,123.622 R291_UB2.2@184.633,125.019 C329_UB2.2@186.436,125.019
NetC330_UB1_2: C330_UB1.2 R292_UB1.2 U50_UB1.3 | length 3.5
  Top Layer w0.254: U50_UB1.3@77.45,99.822 78.943,99.822 79.223,99.543 R292_UB1.2@79.223,101.168
NetC330_UB2_2: C330_UB2.2 R292_UB2.2 U50_UB2.3 | length 3.7
  Top Layer w0.254: U50_UB2.3@189.459,100.355 191.592,100.355 ; R292_UB2.2@191.547,101.067 191.592,101.021 191.592,100.355 ; C330_UB2.2@191.592,99.492 191.592,100.355
NetC369_UB1_1: C369_UB1.1 C370_UB1.1 U54_UB1.46 | length 7.3
  Top Layer w0.254: v1(110.063,78.257) 110.563,77.757 U54_UB1.46@110.563,76.71 110.563,75.39 111.531,74.422 111.836,74.422 112.293,73.965 C369_UB1.1@112.293,72.822
  Bottom Layer w0.254: v1(110.063,78.257) 110.134,78.329 C370_UB1.1@110.134,78.969
NetC369_UB2_1: C369_UB2.1 C370_UB2.1 U54_UB2.46 | length 6.5
  Top Layer w0.254: C369_UB2.1@157.683,71.018 158.592,71.927 U54_UB2.46@158.592,74.723 158.592,76.053 v1(158.572,76.073)
  Bottom Layer w0.254: v1(158.572,76.073) C370_UB2.1@158.572,77.165
NetC384_UB1_2: C384_UB1.2 U54_UB1.8 Y4_UB1.2 | length 7.7
  Top Layer w0.254: U54_UB1.8@113.413,82.06 114.776,82.06 116.129,83.414 116.129,85.344 Y4_UB1.2@117.196,86.411
  Bottom Layer w0.254: C384_UB1.2@116.84,84.734 v1@116.84,85.75
  other v1: 116.815,85.954
NetC384_UB2_2: C384_UB2.2 U54_UB2.8 Y4_UB2.2 | length 8.6
  Top Layer w0.254: U54_UB2.8@161.442,80.073 163.284,80.073 163.906,80.695 163.906,82.423 165.729,84.245 Y4_UB2.2@166.156,84.245
  Bottom Layer w0.254: v1(166.116,83.718) 166.141,83.693 C384_UB2.2@166.141,82.575
NetC390_UB1_2: C390_UB1.2 U54_UB1.7 Y4_UB1.1 | length 5.1
  Top Layer w0.254: U54_UB1.7@113.413,81.56 117.044,81.56 Y4_UB1.1@117.196,81.712
  Bottom Layer w0.254: v1(116.713,82.22) 116.967,82.474 C390_UB1.2@116.967,83.374
NetC390_UB2_2: C390_UB2.2 U54_UB2.7 Y4_UB2.1 | length 5.8
  Top Layer w0.254: U54_UB2.7@161.442,79.573 166.129,79.573 Y4_UB2.1@166.156,79.546
  Bottom Layer w0.254: v1(166.141,80.086) 166.167,80.111 C390_UB2.2@166.167,81.153
NetC403_UB1_1: C403_UB1.1 U55_UB1.102 X2_UB1.2 | length 7.2
  Top Layer w0.254: X2_UB1.2@46.507,49.766 46.464,49.809 47.54,50.886 U55_UB1.102@47.54,54.491
  Bottom Layer w0.254: C403_UB1.1@45.999,47.777 45.999,49.733 X2_UB1.2@46.05,49.784
NetC403_UB2_1: C403_UB2.1 U55_UB2.102 X2_UB2.2 | length 11.2
  Top Layer w0.254: U55_UB2.102@204.385,54.796 204.385,52.79 206.832,50.343 209.956,50.343 X2_UB2.2@210.337,49.962
  Bottom Layer w0.254: X2_UB2.2@210.337,49.962 210.49,49.809 C403_UB2.1@210.49,47.955
NetC404_UB1_1: C404_UB1.1 U55_UB1.104 X2_UB1.1 | length 8.8
  Top Layer w0.254: U55_UB1.104@48.54,54.491 48.54,51.434 50.165,49.809 51.544,49.809 X2_UB1.1@51.613,49.74
  Bottom Layer w0.254: C404_UB1.1@51.029,47.828 51.029,49.682 X2_UB1.1@51.13,49.784
NetC404_UB2_1: C404_UB2.1 U55_UB2.104 X2_UB2.1 | length 14.7
  Top Layer w0.254: U55_UB2.104@205.385,54.796 205.385,52.78 206.934,51.232 213.823,51.232 X2_UB2.1@214.864,50.19
  Bottom Layer w0.254: C404_UB2.1@215.189,47.93 215.417,48.158 X2_UB2.1@215.417,49.962
NetC407_UB1_1: C407_UB1.1 D24_UB1.1 R353_UB1.2 U59_UB1.1 | length 5.7
  Top Layer w0.254: C407_UB1.1@28.753,70.612 30.404,70.612 ; D24_UB1.1@30.226,71.501 30.41,71.316 U59_UB1.1@30.41,68.453 ; 30.429,70.561 D24_UB1.1@30.429,71.45
NetC407_UB2_1: C407_UB2.1 D24_UB2.1 R353_UB2.2 U59_UB2.1 | length 4.6
  Top Layer w0.508: U59_UB2.1@230.804,71.465 230.972,71.298 231.064,71.298 231.14,71.222 231.14,69.367 ; D24_UB2.1@231.14,68.402 231.14,69.367 ; C407_UB2.1@232.461,69.393 231.165,69.393 231.14,69.367
NetC409_UB1_1: C409_UB1.1 R356_UB1.2 R359_UB1.1 U59_UB1.3 | length 4.5
  Top Layer w0.762: C409_UB1.1@27.305,65.888 30.308,65.888 30.536,65.659 30.536,66.873 30.531,66.878
NetC409_UB2_1: C409_UB2.1 R356_UB2.2 R359_UB2.1 U59_UB2.3 | length 5.3
  Top Layer w0.254: R356_UB2.2@230.556,74.32 231.292,74.32 ; U59_UB2.3@230.804,72.826 231.17,72.826 231.292,72.949 231.292,74.32 ; C409_UB2.1@233.979,74.32 R359_UB2.1@232.455,74.32 231.292,74.32
NetC427_1: C427.1 R374.1 R378.1 R379.2 R382.2 | length 6.3
  Top Layer w0.381: C427.1@121.234,97.638 121.285,97.587 R382.2@122.758,97.587 ; R378.1@122.682,94.539 122.682,96.012 R374.1@122.733,96.063 122.733,97.561 R382.2@122.758,97.587 ; R379.2@124.231,98.095 124.028,98.095 123.52,97.587 R382.2@122.758,97.587
NetC440_2: C440.2 R400.2 U67.1 | length 8.5
  Top Layer w0.762: v2(131.47,60.731) U67.1@132.608,60.731 ; C440.2@132.105,55.905 R400.2@132.105,57.302
  Mid-Layer 2 w0.762: v2(131.47,60.731) 131.47,55.702 v2@132.118,55.054
  other v2: 132.156,55.093
NetC441_1: C441.1 R396.1 R399.2 | length 3
  Top Layer w0.254: R399.2@131.135,72.275 132.576,72.275 C441.1@132.588,72.263 R396.1@132.588,70.76
NetC442_1: C442.1 R400.1 R401.2 U67.2 | length 7.9
  Top Layer w0.254: C442.1@130.556,57.424 R401.2@130.556,58.877 ; R400.1@132.105,58.877 R401.2@130.556,58.877 ; U67.2@132.608,62.001 131.115,62.001 130.556,61.443 R401.2@130.556,58.877
NetC442_2: C442.2 R401.1 R404.1 U67.6 | length 9.4
  Top Layer w0.254: U67.6@126.461,63.271 128.071,63.271 128.981,62.361 R401.1@128.981,58.877 ; R404.1@127.432,58.852 128.956,58.852 R401.1@128.981,58.877 ; C442.2@128.981,57.424 R401.1@128.981,58.877
NetC443_1: C443.1 R403.1 R407.2 R408.1 | length 5.5
  Top Layer w0.254: R408.1@126.492,67.793 126.492,69.164 R407.2@126.517,69.19 ; R407.2@126.492,69.215 R407.2@126.517,69.19 ; C443.1@129.083,67.691 R403.1@129.083,69.19 R407.2@126.517,69.19
NetC443_2: C443.2 R396.2 R397.1 R403.2 | length 5.3
  Top Layer w0.254: C443.2@130.658,67.691 132.512,67.691 R397.1@132.588,67.767 R396.2@132.588,69.185 132.583,69.19 R403.2@130.658,69.19
NetC445_1: C445.1 R406.1 R407.1 | length 2.9
  Top Layer w0.254: C445.1@126.467,73.685 126.492,73.66 R407.1@126.492,70.79
NetC446_2: C446.2 R404.2 U67.7 | length 12.2
  Top Layer w0.762: U67.7@126.461,62.001 v2(127.686,62.001) ; C446.2@127.432,55.321 C446.2@127.432,55.524 ; R404.2@127.432,57.277 C446.2@127.432,55.524 ; v2(129.083,55.626) 128.981,55.524 C446.2@127.432,55.524
  Mid-Layer 2 w0.762: v2(127.686,62.001) 127.203,61.519 127.203,59.741 129.083,57.861 v2(129.083,55.626)
NetD13_UB1_1: D13_UB1.1 F1_UB1.2 | length 12.1
  Top Layer w2.54: F1_UB1.2@19.355,23.292 19.355,34.341 D13_UB1.1@20.422,34.341
NetD13_UB2_1: D13_UB2.1 F1_UB2.2 | length 10.5
  Top Layer w2.54: D13_UB2.1@240.843,33.401 241.833,32.41 F1_UB2.2@241.833,23.317
NetD16_UB1_1: D16_UB1.1 R192_UB1.2 R194_UB1.2 | length 4.4
  Top Layer w0.762: D16_UB1.1@44.044,120.142 44.044,118.364 v1(44.069,118.339)
  Bottom Layer w0.762: v1(44.069,118.339) 45.187,118.339 R192_UB1.2@45.212,118.313 R194_UB1.2@46.634,118.313
NetD16_UB2_1: D16_UB2.1 R192_UB2.2 R194_UB2.2 | length 2.8
  Bottom Layer w0.254: R192_UB2.2@212.547,118.999 R194_UB2.2@213.944,118.999
  Bottom Layer w0.508: D16_UB2.1@212.496,120.421 212.496,119.05 R192_UB2.2@212.547,118.999
NetD21_UB1_2: D21_UB1.2 R234_UB1.1 | length 1.5
  Top Layer w0.762: D21_UB1.2@74.905,43.205 76.378,43.205 R234_UB1.1@76.429,43.256
NetD21_UB2_2: D21_UB2.2 R234_UB2.1 | length 1.6
  Top Layer w0.762: R234_UB2.1@192.481,41.097 192.507,41.072 D21_UB2.2@192.507,39.548
NetD23_UB1_2: D23_UB1.2 R262_UB1.1 | length 1.6
  Top Layer w0.254: D23_UB1.2@84.912,46.152 86.487,46.152 R262_UB1.1@86.512,46.177
NetD23_UB2_2: D23_UB2.2 R262_UB2.1 | length 1.8
  Top Layer w0.762: D23_UB2.2@180.137,39.649 180.162,39.649 180.442,39.929 R262_UB2.1@180.442,41.326
NetJP2_UB1_6: JP2_UB1.6
NetJP2_UB2_6: JP2_UB2.6
NetJP3_6: JP3.6
NetJP3_7: JP3.7
NetJP3_8: JP3.8
NetLED1_2: LED1.2 R31.1 | length 1.7
  Top Layer w0.381: R31.1@141.707,121.437 143.408,121.437 LED1.2@143.434,121.463
NetLED2_2: LED2.2 R33.1 | length 1.8
  Top Layer w0.381: R33.1@140.64,112.293 LED2.2@142.392,112.293
NetLED3_2: LED3.2 S1.1 | length 2
  Top Layer w1.016: LED3.2@109.779,130.353 109.804,130.327 S1.1@109.804,128.372
NetLED4_2: LED4.2 S1.2 | length 2
  Top Layer w1.016: S1.2@107.264,128.372 LED4.2@107.264,130.327
NetLED5_UB1_2: LED5_UB1.2 R41_UB1.2 | length 1.6
  Top Layer w0.762: R41_UB1.2@27.991,73.609 LED5_UB1.2@27.991,75.235
NetLED5_UB2_2: LED5_UB2.2 R41_UB2.2 | length 2
  Top Layer w0.508: R41_UB2.2@230.608,65.862 232.435,65.862 LED5_UB2.2@232.537,65.761
NetLED9_UB1_2: LED9_UB1.2 R210_UB1.2 | length 1.7
  Top Layer w0.762: R210_UB1.2@77.47,15.291 LED9_UB1.2@77.47,16.942
NetLED9_UB2_2: LED9_UB2.2 R210_UB2.2 | length 1.7
  Top Layer w0.762: R210_UB2.2@182.982,15.24 LED9_UB2.2@182.982,16.942
NetLED10_UB1_2: LED10_UB1.2 R275_UB1.2 | length 1.7
  Top Layer w0.762: LED10_UB1.2@28.981,126.39 R275_UB1.2@30.709,126.39
NetLED10_UB2_2: LED10_UB2.2 R275_UB2.2 | length 1.8
  Top Layer w0.762: R275_UB2.2@230.115,125.959 LED10_UB2.2@231.953,125.959
NetLED11_UB1_2: LED11_UB1.2 R289_UB1.2 | length 1.7
  Top Layer w0.762: R289_UB1.2@57.328,48.895 59.004,48.895 LED11_UB1.2@59.055,48.946
NetLED11_UB2_2: LED11_UB2.2 R289_UB2.2 | length 1.9
  Top Layer w0.762: LED11_UB2.2@216.306,42.316 216.383,42.24 R289_UB2.2@216.383,40.411
NetLED12_UB1_2: LED12_UB1.2 R330_UB1.2 | length 1.8
  Top Layer w0.762: R330_UB1.2@118.638,54.432 120.34,54.432 LED12_UB1.2@120.416,54.508
NetLED12_UB2_2: LED12_UB2.2 R330_UB2.2 | length 1.8
  Top Layer w1.016: LED12_UB2.2@140.843,54.487 R330_UB2.2@142.596,54.487
NetLED13_UB1_2: LED13_UB1.2 R347_UB1.2 | length 1.5
  Top Layer w0.254: LED13_UB1.2@40.107,48.743 R347_UB1.2@41.58,48.743
NetLED13_UB2_2: LED13_UB2.2 R347_UB2.2 | length 3.3
  Top Layer w0.254: LED13_UB2.2@193.548,53.899 195.047,53.899 R347_UB2.2@196.291,52.654
NetLED14_UB1_2: LED14_UB1.2 R365_UB1.2 | length 1.5
  Top Layer w0.762: LED14_UB1.2@109.195,28.956 109.195,30.373 R365_UB1.2@109.251,30.429
NetLED14_UB2_2: LED14_UB2.2 R365_UB2.2 | length 1.4
  Top Layer w0.381: R365_UB2.2@147.029,18.161 147.08,18.212 LED14_UB2.2@147.08,19.558
NetLED15_UB1_2: LED15_UB1.2 R371_UB1.2 | length 1.6
  Top Layer w0.254: LED15_UB1.2@105.918,15.824 R371_UB1.2@107.544,15.824
NetLED15_UB2_2: LED15_UB2.2 R371_UB2.2 | length 1.4
  Top Layer w0.381: LED15_UB2.2@147.08,30.81 147.08,29.425 R371_UB2.2@147.091,29.413
NetLED16_2: LED16.2 R377.1 | length 1.7
  Top Layer w1.27: LED16.2@115.875,94.869 117.551,94.869 R377.1@117.577,94.894
NetLED17_2: LED17.2 R387.1 | length 1.8
  Top Layer w0.762: R387.1@145.186,128.143 LED17.2@146.939,128.143
NetLED18_2: LED18.2 R390.2 | length 1.8
  Top Layer w0.254: LED18.2@126.822,103.581 R390.2@126.822,105.334
NetLED19_2: LED19.2 R395.2 | length 1.8
  Top Layer w0.762: LED19.2@127.045,129.235 127.102,129.179 R395.2@127.102,127.457
NetLED20_2: LED20.2 R431.2 | length 1.6
  Top Layer w0.381: R431.2@121.768,122.657 121.768,124.231 LED20.2@121.818,124.282
NetLED21_2: LED21.2 R435.2 | length 1.5
  Top Layer w1.27: LED21.2@138.303,123.673 138.354,123.622 R435.2@138.354,122.174
NetP2_UB1_2: P2_UB1.2 R29_UB1.2 | length 2.4
  Bottom Layer w0.254: P2_UB1.2@30.836,84.226 32.945,84.226 R29_UB1.2@33.147,84.023
NetP2_UB1_3: P2_UB1.3 R30_UB1.1 | length 2.5
  Bottom Layer w0.254: P2_UB1.3@30.836,81.686 30.913,81.763 R30_UB1.1@33.274,81.763
NetP2_UB2_2: P2_UB2.2 R29_UB2.2 | length 3.4
  Bottom Layer w0.254: R29_UB2.2@226.797,83.972 230.124,83.972 P2_UB2.2@230.149,83.998
NetP2_UB2_3: P2_UB2.3 R30_UB2.1 | length 3.3
  Bottom Layer w0.254: R30_UB2.1@226.873,86.436 230.048,86.436 P2_UB2.3@230.149,86.538
NetP3_UB1_9: P3_UB1.9
NetP3_UB1_10: P3_UB1.10
NetP3_UB1_22: P3_UB1.22
NetP3_UB1_24: P3_UB1.24
NetP3_UB1_25: P3_UB1.25
NetP3_UB2_9: P3_UB2.9
NetP3_UB2_10: P3_UB2.10
NetP3_UB2_22: P3_UB2.22
NetP3_UB2_24: P3_UB2.24
NetP3_UB2_25: P3_UB2.25
NetQ2_UB1_1: Q2_UB1.1 R260_UB1.1 R264_UB1.1 | length 5
  Bottom Layer w0.762: R260_UB1.1@23.546,100.863 23.546,99.619 23.647,99.517 24.872,99.517 Q2_UB1.1@25.355,99.035 25.507,98.882 R264_UB1.1@27,98.882
NetQ2_UB1_3: Q2_UB1.3 R250_UB1.1 | length 2.4
  Bottom Layer w0.762: R250_UB1.1@21.387,99.009 22.479,99.009 23.393,98.095 Q2_UB1.3@23.424,98.095
NetQ2_UB2_1: Q2_UB2.1 R260_UB2.1 R264_UB2.1 | length 3
  Bottom Layer w0.254: R260_UB2.1@227.838,101.219 227.863,101.244 R264_UB2.1@229.387,101.244 ; R264_UB2.1@229.438,101.143 Q2_UB2.1@230.886,101.143
NetQ2_UB2_3: Q2_UB2.3 R250_UB2.1 | length 8.2
  Bottom Layer w0.254: R250_UB2.1@227.178,97.815 230.683,97.815 232.816,99.949 232.816,101.676
NetR6_2: R6.2 U1.3 | length 41.4
  Top Layer w0.254: v1(138.379,67.894) 138.659,68.174 R6.2@138.659,69.164 ; U1.3@139.7,30.963 v1(139.7,32.893)
  Mid-Layer 2 w0.254: 136.855,41.529 136.855,40.462 ; v1(136.931,47.676) 136.855,47.6 136.855,40.462 ; v1(139.7,32.893) 139.7,33.198 137.719,35.179 137.719,39.599 136.855,40.462
  Bottom Layer w0.254: v1(136.931,47.676) 137.465,48.209 137.465,66.954 138.455,67.945 138.43,67.945 v1(138.379,67.894)
NetR7_2: R7.2 U1.1 | length 45.3
  Top Layer w0.254: v1(140.056,67.894) 140.081,67.92 R7.2@140.081,69.19 ; v1(142.215,32.36) 142.24,32.334 U1.1@142.24,30.963
  Mid-Layer 2 w0.254: 137.617,42.545 137.617,40.716 ; v1(137.617,47.092) 137.617,40.716 ; v1@142.201,32.36 v1(142.215,32.36) 141.046,33.528 140.183,33.528 139.548,34.163 139.548,38.786 137.617,40.716
  Bottom Layer w0.254: v1(137.617,47.092) 138.125,47.6 138.125,53.391 138.735,54 ; 138.506,53.696 138.735,53.924 138.735,54 ; 138.735,55.397 138.735,54 ; v1(140.056,67.894) 140.056,67.589 138.735,66.269 138.735,54
NetR8_2: R8.2 U1.2 | length 43.2
  Top Layer w0.254: v1(137.185,67.894) R8.2@137.185,69.139 ; v1(140.945,32.385) 140.97,32.36 U1.2@140.97,30.963
  Mid-Layer 2 w0.254: 136.195,41.173 136.195,40.107 ; v1(136.195,48.438) 136.195,40.107 ; 137.3,34.938 137.008,35.23 ; v1(140.945,32.385) 140.97,32.36 140.97,32.309 139.268,32.309 138.913,32.664 138.913,33.325 137.008,35.23 ; 136.195,40.107 137.008,39.294 137.008,35.23
  Bottom Layer w0.254: v1(136.195,48.438) 136.881,49.124 136.881,67.589 v1(137.185,67.894)
NetR9_2: R9.2 U1.4 | length 40.2
  Top Layer w0.254: v1(135.763,67.945) R9.2@135.763,69.139 ; v1(138.328,32.741) 138.328,32.791 138.43,32.69 U1.4@138.43,30.963
  Mid-Layer 2 w0.254: v1(135.865,49.555) 135.357,49.047 135.357,35.865 v1@138.405,32.817
  Bottom Layer w0.254: v1(135.763,67.945) 135.763,63.906 136.423,63.246 136.423,60.604 136.271,60.452 136.271,49.962 v1(135.865,49.555)
NetR10_2: R10.2 U2.1 | length 2.6
  Top Layer w0.381: R10.2@132.131,22.327 132.105,22.352 132.105,23.419 132.512,23.825 U2.1@132.512,24.74
NetR11_2: R11.2 U2.3 | length 2.4
  Top Layer w0.381: U2.3@135.052,24.74 135.052,22.377 R11.2@135.077,22.352
NetR13_2: R13.2 U2.2 | length 2.5
  Top Layer w0.381: R13.2@133.579,22.327 133.782,22.53 U2.2@133.782,24.74
NetR14_2: R14.2 U2.4 | length 2.5
  Top Layer w0.381: U2.4@136.322,24.74 136.322,22.555 R14.2@136.55,22.327
NetR23_UB1_2: R23_UB1.2 U43_UB1.1 | length 2.9
  Top Layer w0.254: R23_UB1.2@62.89,103.556 62.89,106.446 U43_UB1.1@62.896,106.451
NetR23_UB2_2: R23_UB2.2 U43_UB2.1 | length 2.6
  Bottom Layer w0.254: R23_UB2.2@198.557,104.089 U43_UB2.1@198.557,106.705
NetR26_UB1_2: R26_UB1.2 U3_UB1.1 | length 9.2
  Bottom Layer w0.254: U3_UB1.1@38.176,105.664 38.176,104.445 38.583,104.038 41.453,104.038 43.643,101.849 R26_UB1.2@43.643,100.432
NetR26_UB2_2: R26_UB2.2 U3_UB2.1 | length 7.6
  Bottom Layer w0.254: R26_UB2.2@219.812,106.959 220.548,107.696 225.273,107.696 225.654,107.315 U3_UB2.1@225.654,106.045
NetR27_UB1_2: R27_UB1.2 U3_UB1.3 | length 10
  Bottom Layer w0.254: U3_UB1.3@35.636,105.664 35.636,104.953 37.338,103.251 40.843,103.251 42.093,102.001 R27_UB1.2@42.093,100.432
NetR27_UB2_2: R27_UB2.2 U3_UB2.3 | length 3.7
  Bottom Layer w0.254: R27_UB2.2@220.167,105.156 222.961,105.156 223.114,105.308 U3_UB2.3@223.114,106.045
NetR28_UB1_1: R28_UB1.1 U3_UB1.5 | length 2.9
  Bottom Layer w0.508: U3_UB1.5@36.906,116.713 R28_UB1.1@36.906,119.583
NetR28_UB2_1: R28_UB2.1 U3_UB2.5 | length 2.4
  Bottom Layer w0.381: R28_UB2.1@224.358,119.532 224.384,119.507 U3_UB2.5@224.384,117.094
NetR39_UB1_2: R39_UB1.2 U54_UB1.20 | length 6.2
  Top Layer w0.254: v1(105.283,85.928) 105.283,84.988 105.816,84.455 107.772,84.455 108.063,84.746 U54_UB1.20@108.063,85.91
  Bottom Layer w0.254: v1(105.283,85.928) R39_UB1.2@105.283,86.919
NetR39_UB2_2: R39_UB2.2 U54_UB2.20 | length 4.7
  Top Layer w0.254: v1@153.772,82.601 155.88,82.601 156.092,82.813 U54_UB2.20@156.092,83.923
  Bottom Layer w0.254: R39_UB2.2@153.111,83.49 153.111,83.287 v1(153.772,82.626)
NetR40_UB1_2: R40_UB1.2 U42_UB1.20 | length 6.3
  Top Layer w0.254: v1(99.771,63.398) 100.635,62.535 102.616,62.535 103.049,62.967 U42_UB1.20@103.049,63.985
  Bottom Layer w0.254: R40_UB1.2@99.517,64.77 99.517,63.652 v1(99.771,63.398)
NetR40_UB2_2: R40_UB2.2 U42_UB2.20 | length 6.1
  Top Layer w0.254: v1(154,62.103) 154,61.468 154.407,61.062 155.487,61.062 155.512,61.036 156.642,61.036 156.984,61.378 U42_UB2.20@156.984,62.25
  Bottom Layer w0.254: R40_UB2.2@153.67,63.297 153.67,62.433 v1(154,62.103)
NetR187_1: R187.1 R417.1 U69.13 U69.14 | length 7.3
  Top Layer w0.381: U69.14@126.447,38.824 127.825,38.824 128.041,39.04 128.041,40.03 127.953,40.119 U69.13@126.447,40.119
  Bottom Layer w0.381: R187.1@126.492,40.335 126.543,40.284 R417.1@129.464,40.284
  other v2: 127.991,40.183
NetR188_1: R188.1 R429.1 U69.8 U69.9 | length 8.7
  Top Layer w0.254: U69.8@126.421,46.444 127.673,46.444 v1(127.686,46.457) ; U69.9@126.447,45.174 127.495,45.174 127.686,45.364 v1(127.686,46.457) ; v1(129.134,47.117) 129.134,46.888 128.702,46.457 v1(127.686,46.457)
  Bottom Layer w0.254: R188.1@127.051,48.057 127.051,47.549 127.686,46.914 v1(127.686,46.457) ; 129.438,47.193 129.438,47.244 130.15,47.955 R429.1@130.15,48.184
NetR194_UB1_1: R194_UB1.1 U35_UB1.2 | length 2
  Bottom Layer w0.762: R194_UB1.1@46.634,116.738 46.634,114.788 U35_UB1.2@46.64,114.783
NetR194_UB2_1: R194_UB2.1 U35_UB2.2 | length 2.4
  Bottom Layer w0.254: U35_UB2.2@213.792,115.189 213.792,117.221 R194_UB2.1@214.02,117.45
NetR196_UB1_2: R196_UB1.2 U32_UB1.3 | length 4.8
  Top Layer w0.254: R196_UB1.2@103.088,44.12 103.088,41.616 103.607,41.097 U32_UB1.3@105.12,41.097
NetR196_UB2_2: R196_UB2.2 U32_UB2.3 | length 11.1
  Top Layer w0.381: U32_UB2.3@156.362,34.823 v2(156.362,35.916)
  Top Layer w0.762: R196_UB2.2@164.109,40.011 R196_UB2.2@164.109,40.361
  Mid-Layer 2 w0.381: v2(156.362,35.916) 159.512,35.916 v1(164.109,40.513)
NetR215_UB1_2: R215_UB1.2 U37_UB1.1 | length 3
  Top Layer w0.254: R215_UB1.2@51.44,103.581 U37_UB1.1@51.44,106.604
NetR215_UB2_2: R215_UB2.2 U37_UB2.1 | length 2.6
  Bottom Layer w0.254: U37_UB2.1@209.6,106.68 U37_UB2.1@209.6,106.68 R215_UB2.2@209.601,104.115
NetR218_UB1_2: R218_UB1.2 U38_UB1.1 | length 2.9
  Bottom Layer w0.254: U38_UB1.1@65.43,106.451 65.456,106.426 R218_UB1.2@65.456,103.556
NetR218_UB2_2: R218_UB2.2 U38_UB2.1 | length 2.6
  Top Layer w0.254: R218_UB2.2@196.012,104.089 196.012,106.7 U38_UB2.1@196.017,106.705
NetR222_UB1_2: R222_UB1.2 U32_UB1.5 | length 2.3
  Top Layer w0.254: U32_UB1.5@98.973,42.367 99.365,42.367 U32_UB1.5@99.466,42.469 ; 99.593,42.596 99.593,42.988 ; 99.593,43.205 99.593,42.988 ; R222_UB1.2@99.593,44.12 99.593,42.988
NetR222_UB2_2: R222_UB2.2 U32_UB2.5 | length 2.9
  Top Layer w0.762: U32_UB2.5@157.632,40.97 157.632,40.03 157.759,39.903 159.436,39.903 R222_UB2.2@159.512,39.98
NetR223_UB1_1: R223_UB1.1 U38_UB1.5 | length 2.8
  Bottom Layer w0.254: U38_UB1.5@64.16,117.5 R223_UB1.1@64.16,120.294
NetR223_UB2_1: R223_UB2.1 U38_UB2.5 | length 2.4
  Top Layer w0.254: U38_UB2.5@197.287,117.754 R223_UB2.1@197.287,120.167
NetR224_UB1_1: R224_UB1.1 U37_UB1.5 | length 3
  Top Layer w0.254: U37_UB1.5@52.71,117.653 R224_UB1.1@52.71,120.675
NetR224_UB2_1: R224_UB2.1 U37_UB2.5 | length 2.7
  Bottom Layer w0.254: U37_UB2.5@208.33,117.729 R224_UB2.1@208.33,120.396
NetR226_UB1_2: R226_UB1.2 U37_UB1.3 | length 3
  Top Layer w0.254: R226_UB1.2@53.98,103.581 U37_UB1.3@53.98,106.604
